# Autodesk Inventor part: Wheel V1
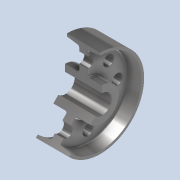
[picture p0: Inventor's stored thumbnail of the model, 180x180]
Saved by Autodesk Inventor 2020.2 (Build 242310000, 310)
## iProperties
Created: 2018-06
Part Number: Wheel V1
Material: Stainless Steel
Document SubType Name: Modeling
Designer: Power User
Density: 8 g/cm^3
Appearance: Semi-Polished
Mass: 618.44 g
Surface Area: 270.831 cm^2
Volume: 77.305 cm^3
Author: Power User
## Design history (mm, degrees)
sketch "Sketch1"
  geometry: L1 (-34.726, 0)-(34.726, 0); L2 (0, 36.063)-(0, -36.063); L3 (0, 11)-(-21, 11); L4 (-21, 19)-(-5, 19); L5 (-5, 19)-(-5, 45.032); L6 (-5, 45.032)-(-19, 47); L7 (-19, 47)-(-19, 50); L8 (-19, 50)-(0, 50); L9 (-21, 19)-(-21, 11); L10 (0, 11)-(21, 11); L11 (21, 19)-(5, 19); L12 (5, 19)-(5, 45.032); L13 (5, 45.032)-(19, 47); L14 (19, 47)-(19, 50); L15 (19, 50)-(0, 50); L16 (21, 19)-(21, 11); 2 further points
  constraints: 32 end point, 6 symmetric about line, 3 perpendicular, 2 horizontal, 2 midpoint, 2 point on line, 2 vertical, 1 coincident, 1 other
  dimensions: "d4" = 19 distance of L7.end L8.end; "d5" = 10 diameter of L5 L2; "d6" = 8 deg angle of L4 L6; "d7" = 42 diameter of L9 L2; "d24" = 11 distance from line of L3 point (0, 0); "d25" = 19 distance from line of L4 point (0, 0); "d26" = 47 vertical distance of L6.end point (0, 0); "d27" = 50 distance from line of point (0, 0) L8
revolve "Revolution1" sketch "Sketch1" stored, may be unused: angle "d8" = 225 deg; dims "d9" = 45 deg
sketch "Sketch2" dims "d12" = 33.2
  geometry: C1 r 6.1 at (0, 14.2); C2 r 6.1 at (-23.476, 4.476); C3 r 6.1 at (-33.2, -19); C4 r 6.1 at (-23.476, -42.476); C5 r 6.1 at (0, -52.2); C6 r 6.1 at (23.476, -42.476); C7 r 6.1 at (33.2, -19); C8 r 6.1 at (23.476, 4.476); 2 further points
  constraints: 8 centre point, 2 vertical alignment, 1 coincident, 19 other
  dimensions: "d10" = 12.2 diameter of C1; "d15" = 360 deg dimension on point (0, -19) C1.centre (derived)
hole "Hole1" sketch "Sketch2" at (23.476, 4.476), (33.2, -19), (23.476, -42.476), (0, -52.2), (-23.476, -42.476), (0, 14.2) diameter "d17" = 12.2; stored, may be unused: countersink angle "d21" = 90 deg, drill point angle "d23" = 118 deg; dims "d18" = 6, "d19" = 20, "d20" = 2, "d22" = 8
fillet "Fillet1" dims "d28" = 2
workplane "Work Plane1"
body "Solid1"
